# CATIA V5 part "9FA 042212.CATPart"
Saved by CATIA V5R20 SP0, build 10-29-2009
Part number: 9FA 042212
Revision: ANY
Definition: UNKNOWN
Nomenclature: 9FA 042212
Source: Unknown
Bounding box of the stored display mesh (mm): x -2 to 2, y 0.1 to 12.1, z -2 to 2
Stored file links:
  C:\Users\Utente\Desktop\IO LAVORO\3D X SITO CF\CUMSA\3D files FA\FA 0422SF\9FA 042212.CATPart

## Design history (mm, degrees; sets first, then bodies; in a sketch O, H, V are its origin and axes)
Set1 "FacciaKO#NONE#7801"
  DatumSurface1 "Sup7801_1"
  DatumCurve1 "Crv7801_1"
Body1 "Cortar-Extruir3" (main body)
  Solid1: solid without history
